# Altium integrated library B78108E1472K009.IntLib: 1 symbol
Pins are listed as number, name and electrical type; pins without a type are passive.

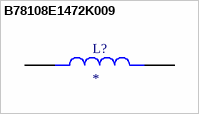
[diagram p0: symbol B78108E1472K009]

## B78108E1472K009
designator L?
4.7 ÂµH Unshielded Drum Core, Wirewound Inductor 2.75 A 85mOhm Max Axial; MP: B78108E1472K009; MF: EPCOS
footprint INDAD1430W80L950D400
pins: 1, 2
